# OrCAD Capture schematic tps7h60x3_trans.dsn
size B; title: TPS7H60x3 Radiation-Hardness-Assured Half-Bridge; rev: *; note: Datasheet: SNOSDE3    EVM User Guide: SLVUCN5; note: GaN FET Driver
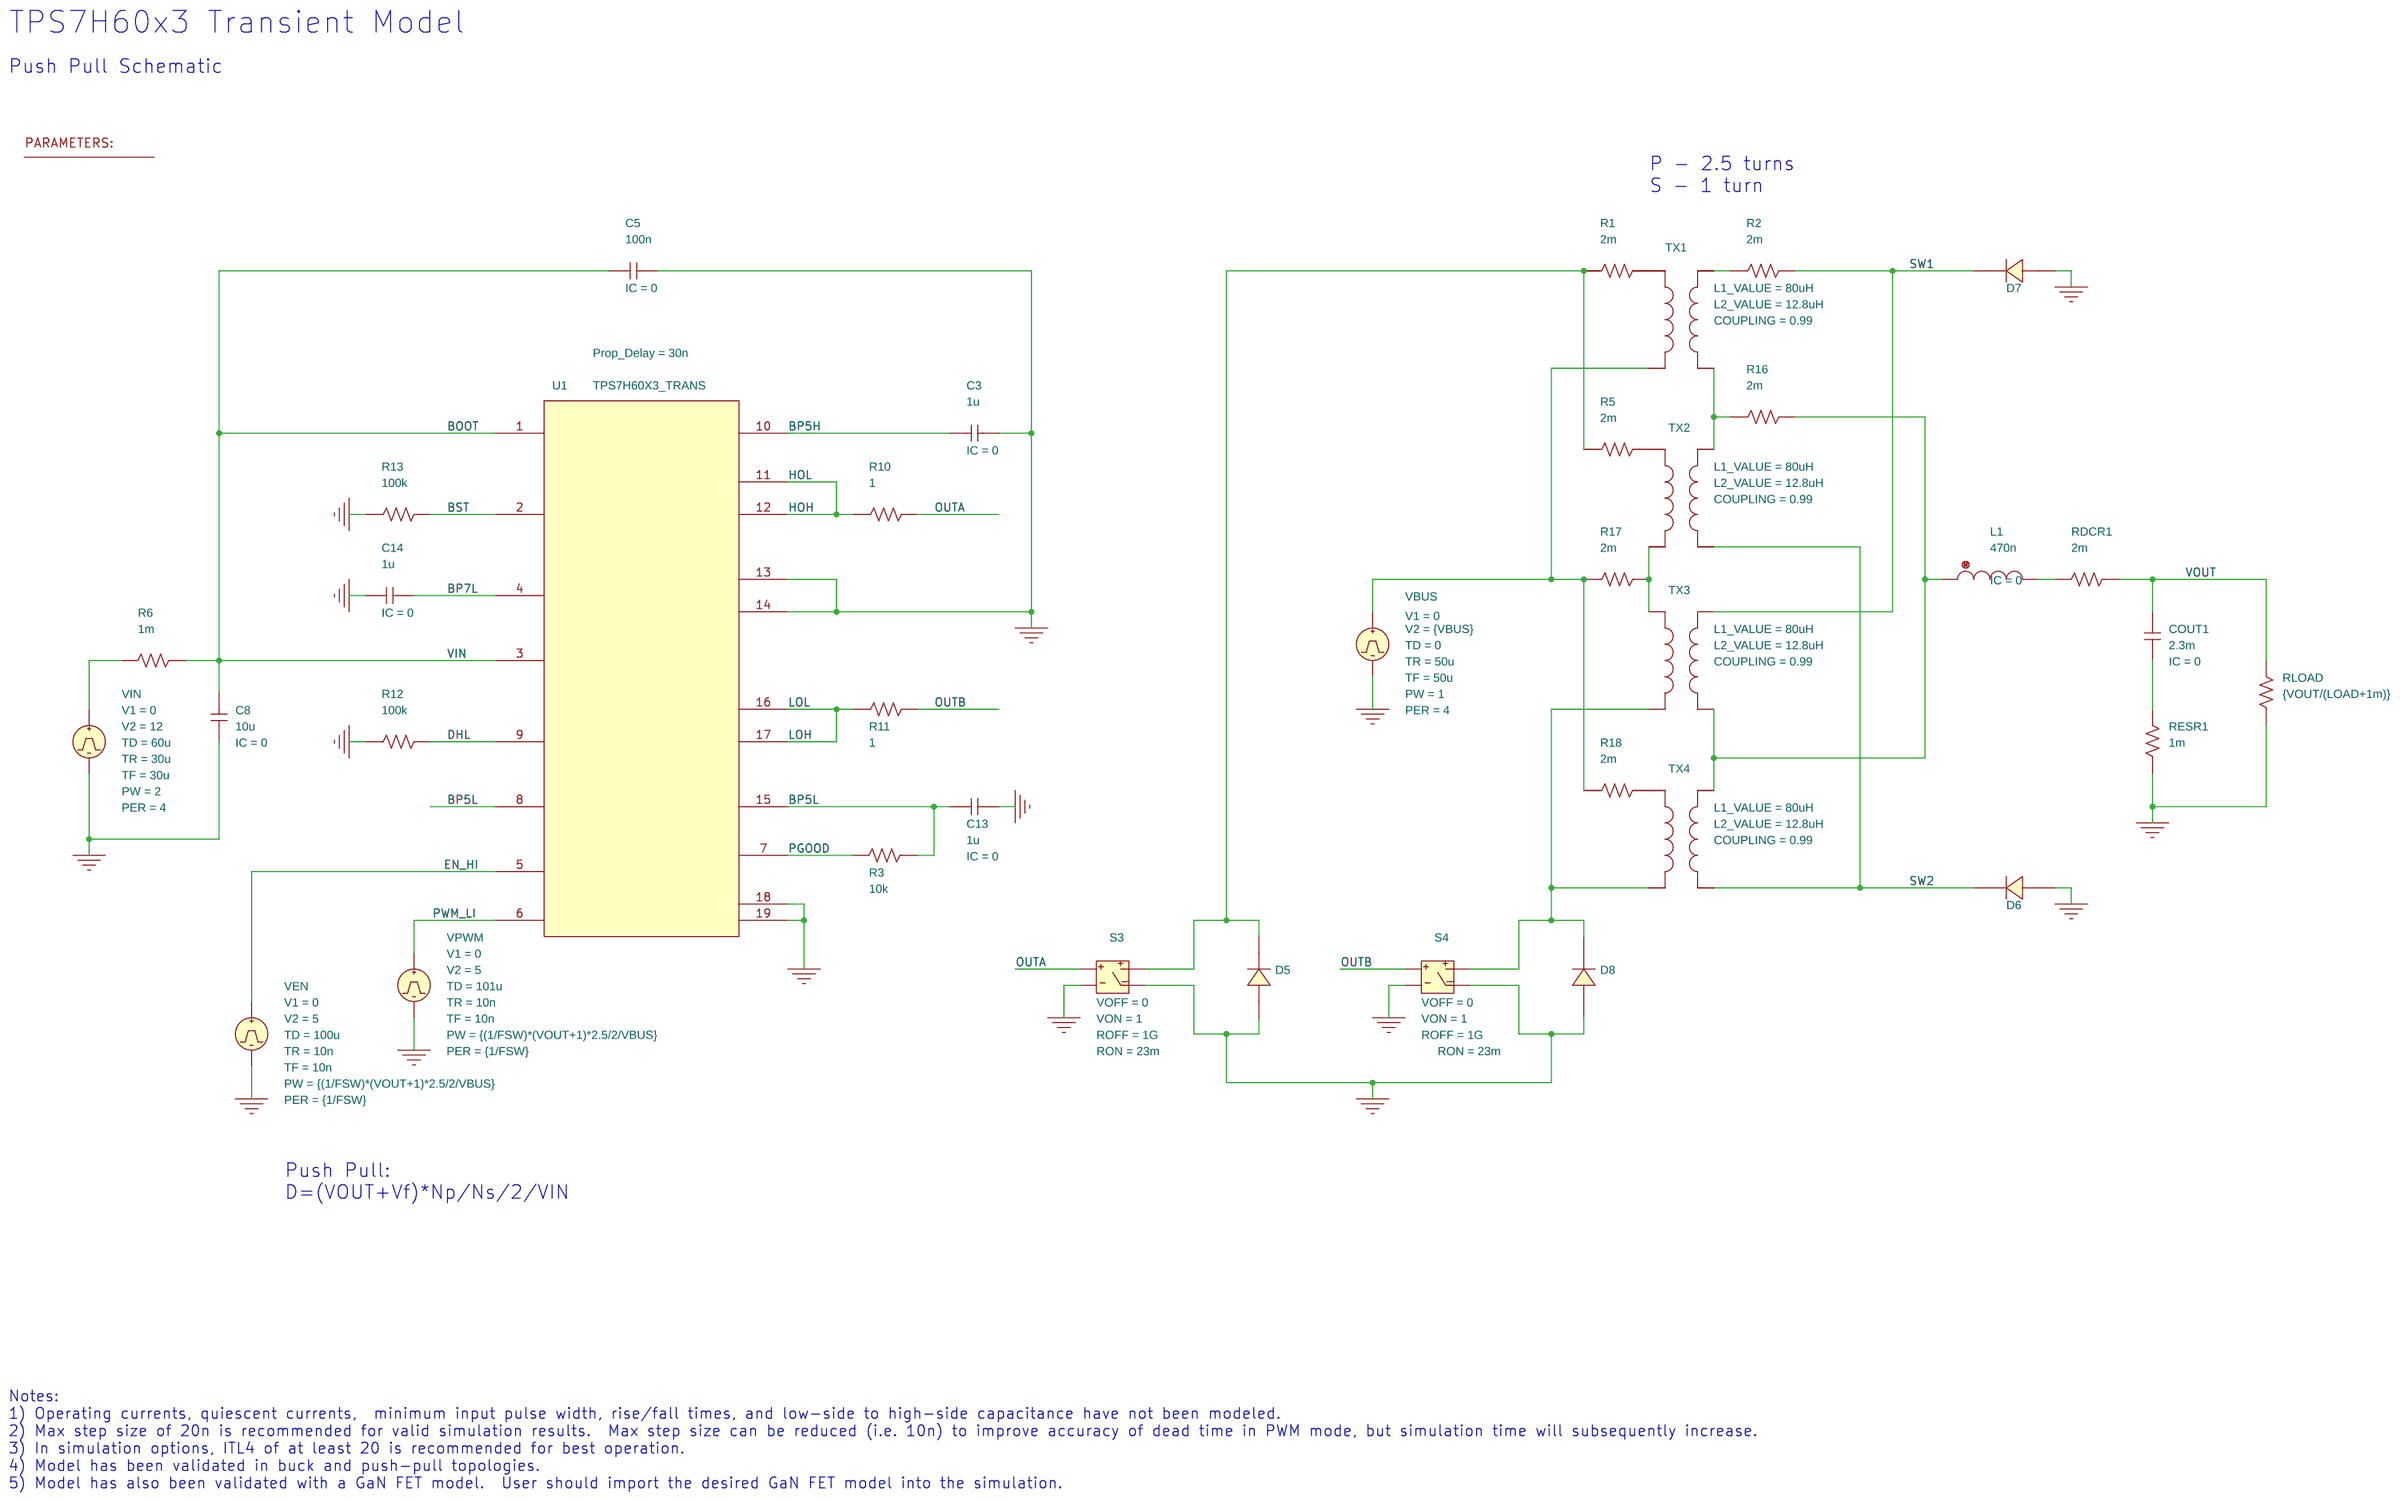
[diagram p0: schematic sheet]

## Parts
1  PARAM
C3  1u  [cap196]
C5  100n  [cap196]
C8  10u  [cap196]
C13  1u  [cap196]
C14  1u  [cap196]
COUT1  2.3m  [cap196]
D5  D_D1  [DO41]
D6  D_D1  [DO41]
D7  D_D1  [DO41]
D8  D_D1  [DO41]
L1  470n  [DISC350x175LS200x100034]
R1  2m  [AXRC05]
R2  2m  [AXRC05]
R3  10k  [AXRC05]
R5  2m  [AXRC05]
R6  1m  [AXRC05]
R10  1  [AXRC05]
R11  1  [AXRC05]
R12  100k  [AXRC05]
R13  100k  [AXRC05]
R16  2m  [AXRC05]
R17  2m  [AXRC05]
R18  2m  [AXRC05]
RDCR1  2m  [AXRC05]
RESR1  1m  [AXRC05]
RLOAD  {VOUT/(LOAD+1m)}  [AXRC05]
S3  S
S4  S
TX1  XFRM_LINEAR
TX2  XFRM_LINEAR
TX3  XFRM_LINEAR
TX4  XFRM_LINEAR
U1  TPS7H60X3_TRANS
VBUS  VPULSE
VEN  VPULSE
VIN  VPULSE
VPWM  VPULSE

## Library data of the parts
1 = PARAM: FSW: 500k; LOAD: 5; VBUS: 28; VOUT: 5
C3 C5 C8 C13 C14 COUT1 = C: IC: 0
D5-D8 = D_D1
L1 = L: IC: 0
R1-R3 R5 R6 R10-R13 R16-R18 RDCR1 RESR1 RLOAD = R
S3 S4 = S: ROFF: 1G; RON: 23m; VOFF: 0; VON: 1
TX1-TX4 = XFRM_LINEAR: COUPLING: 0.99; L1_VALUE: 80uH; L2_VALUE: 12.8uH
U1 = TPS7H60X3_TRANS_7: PSpiceTemplate: X^@REFDES  %BOOT %BST %VIN %BP7L %EN_HI %PWM_LI %PGOOD %DLH %DHL %BP5H %HOL %HOH %PSW %ASW %BP5L %LOL %LOH %PGND %AGND @MODEL PARAMS: ?Prop_Delay|Prop_Delay=@Prop_Delay||Prop_Delay=30n|; Prop_Delay: 30n
VBUS = VPULSE: PER: 4; PW: 1; TD: 0; TF: 50u; TR: 50u; V1: 0; V2: {VBUS}
VEN = VPULSE: PER: {1/FSW}; PW: {(1/FSW)*(VOUT+1)*2.5/2/VBUS}; TD: 100u; TF: 10n; TR: 10n; V1: 0; V2: 5
VIN = VPULSE: PER: 4; PW: 2; TD: 60u; TF: 30u; TR: 30u; V1: 0; V2: 12
VPWM = VPULSE: PER: {1/FSW}; PW: {(1/FSW)*(VOUT+1)*2.5/2/VBUS}; TD: 101u; TF: 10n; TR: 10n; V1: 0; V2: 5

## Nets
0: C3.2 C5.2 C8.2 C13.2 C14.1 D5.2(A) D6.2(A) D7.2(A) D8.2(A) R12.1 R13.1 RESR1.1 RLOAD.1 S3.1(2) S3.3(4) S4.1(2) S4.3(4) U1.13(PSW) U1.14(ASW) U1.18(PGND) U1.19(AGND) VBUS.2(-) VEN.2(-) VIN.2(-) VPWM.2(-)
BOOT: C5.1 C8.1 R6.1 U1.1(BOOT) U1.3(VIN)
BP5H: C3.1 U1.10(BP5H)
BP5L: C13.1 R3.1 U1.8(DLH) U1.15(BP5L)
BP7L: C14.2 U1.4(BP7L)
BST: R13.2 U1.2(BST)
DHL: R12.2 U1.9(DHL)
EN_HI: U1.5(EN_HI) VEN.1(+)
HOH: R10.1 U1.11(HOL) U1.12(HOH)
LOH: R11.1 U1.16(LOL) U1.17(LOH)
OUTA: R10.2 S3.0(1)
OUTB: R11.2 S4.0(1)
PGOOD: R3.2 U1.7(PGOOD)
PWM_LI: U1.6(PWM_LI) VPWM.1(+)
SW1: D7.1(C) R2.2 TX3.3
SW2: D6.1(C) TX2.4 TX4.4
VOUT: COUT1.1 RDCR1.1 RLOAD.2
N01900: D5.1(C) R1.1 R5.1 S3.2(3)
N01946: R2.1 TX1.3
N01988: R17.1 R18.1 TX1.2 VBUS.1(+)
N01998: R16.1 TX1.4 TX2.3
N02148: L1.1 R16.2 TX3.4 TX4.3
N02334: R17.2 TX2.2 TX3.1
N02488: L1.2 RDCR1.2
N02678: R6.2 VIN.1(+)
N02704: COUT1.2 RESR1.2
N02812: D8.1(C) S4.2(3) TX3.2 TX4.2
N03832: R1.2 TX1.1
N03833: R5.2 TX2.1
N03834: R18.2 TX4.1

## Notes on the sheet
- TPS7H60x3 Transient Model
- Push Pull Schematic
- P - 2.5 turns
  S - 1 turn
- Push Pull:
  D=(VOUT+Vf)*Np/Ns/2/VIN
- Notes:
  1) Operating currents, quiescent currents,  minimum input pulse width, rise/fall times, and low-side to high-side capacitance have not been modeled.
  2) Max step size of 20n is recommended for valid simulation results.  Max step size can be reduced (i.e. 10n) to improve accuracy of dead time in PWM mode, but simulation time will subsequently increase.
  3) In simulation options, ITL4 of at least 20 is recommended for best operation.
  4) Model has been validated in buck and push-pull topologies.
  5) Model has also been validated with a GaN FET model.  User should import the desired GaN FET model into the simulation.
